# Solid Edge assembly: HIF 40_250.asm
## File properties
Title: Zylinder
Author: ahadarics
Template: iso assembly.asm
Last saved by: ahadarics
Revision: 47
Application: Solid Edge
Username: ahadarics
Dokumentum tartalom típus: 1
Document Number: HIF 40/250
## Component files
Kit_2.par
Kit_1.par
Profilrohr 40_250.par
Mutter.par
Kolbenstange 40_250.par
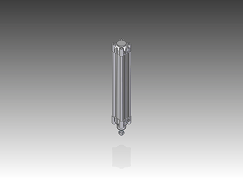
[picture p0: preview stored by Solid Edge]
